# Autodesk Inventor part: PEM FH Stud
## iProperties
Author: John A. Hunter
Shininess: 64.0
Angle Display Precision: 2
Document Length Units: 11272
Document Angle Units: 11286
Document Time Units: 11279
Document Mass Units: 11290
Document Length Units Precision: 3
Document Angle Units Precision: 2
Compacted: True
PropertySet Name: _Private Model Information
Created: 2002-08
Part Number: PEM FH Stud
Material: Steel, High Strength Low Alloy
Description: FH-832-8
Vendor: PEM
Document SubType Name: Modeling
Designer: John A. Hunter
Control State: 0
Master: False
Checked Out: False
PropertySet Name: Design Tracking Control
Density: 0.0
Volumn: 0.0
Area: 0.0
PropertySet Name: Model Information
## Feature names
1. Extrusion1
2. Extrusion2
